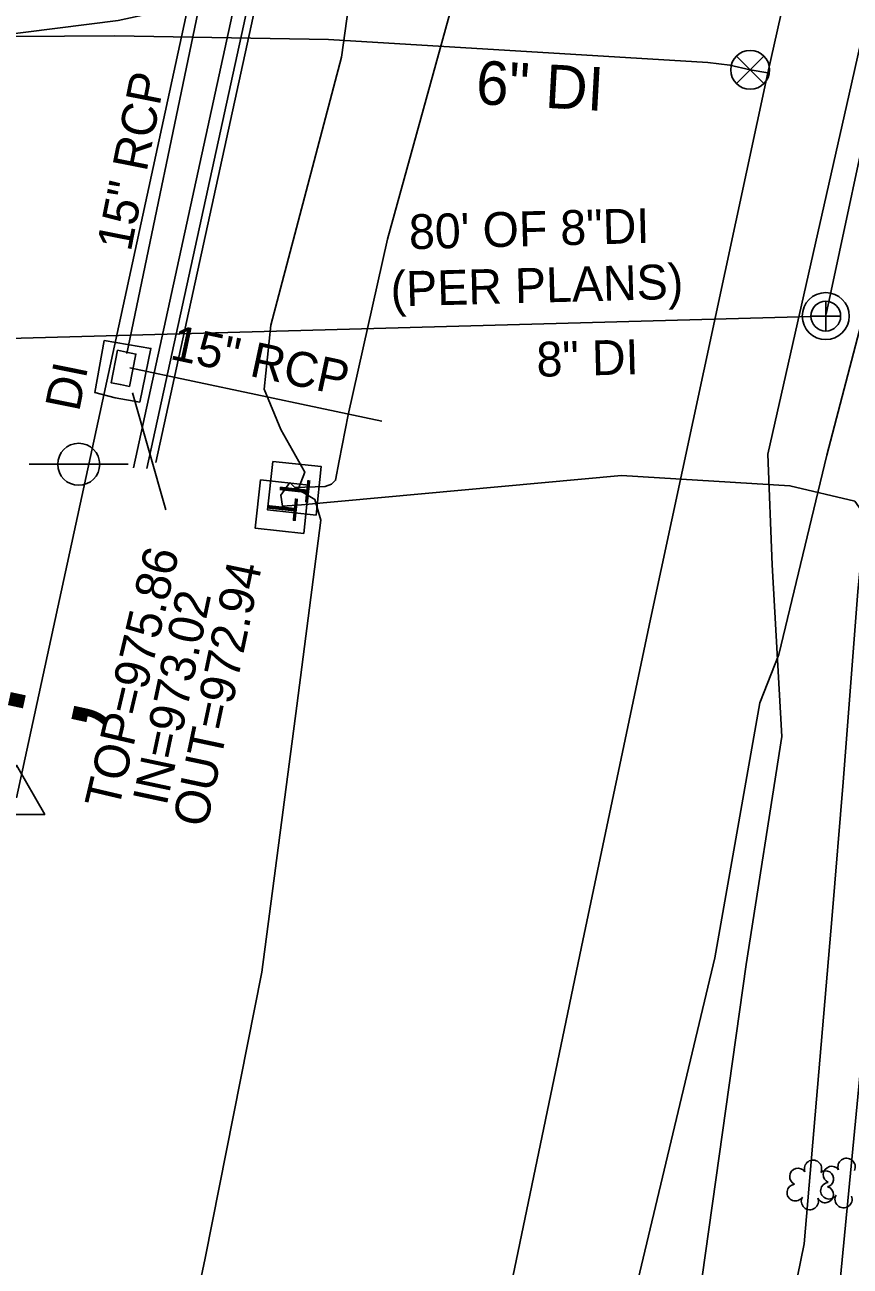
# Model space of a CAD drawing. Extents: x 1614611 to 1617571, y 898867 to 905462.
# Drawn here: x 1616119.9 to 1616214.6, y 899521.1 to 899663.5 of the extents above; entities that cross this region are included whole.
import ezdxf

# ---------------------------------------------------------------- set-up
doc = ezdxf.new("R2010")
doc.units = 0
for name, color, linetype in [('Exist Other Culture Area Outline', 7, 'Continuous'), ('Exist Right of Way Control of Access CA Symbol CELL', 7, 'Continuous'), ('Exist Right of Way Monument CELL', 7, 'Continuous'), ('Exist Structure Minor Drop Inlet Top Elevation', 7, 'Continuous'), ('Exist Structure Minor Pipes RCP 15 Inch Invert', 7, 'Continuous'), ('Exist Utilities Gas UG Line SUE LOS B', 7, 'Continuous'), ('Exist Utilities Sanitary Sewer UG Line', 7, 'Continuous'), ('Exist Utilities Sanitary Sewer UG Line Text', 7, 'Continuous'), ('Exist Utilities Telephone Pedestal CELL', 7, 'Continuous'), ('Exist Utilities Telephone Pole CELL', 7, 'Continuous'), ('Exist Utilities Telephone UG Cable SUE LOS B', 7, 'Continuous'), ('Exist Utilities Telephone UG Cable SUE LOS C', 7, 'Continuous'), ('Exist Utilities Telephone UG FO SUE LOS B', 7, 'Continuous'), ('Exist Utilities Water UG Line SUE LOS B', 7, 'Continuous'), ('Exist Utilities Water UG Line SUE LOS B Text', 7, 'Continuous'), ('Exist Vegetation Shrub CELL', 7, 'Continuous'), ('Old_Level_21', 7, 'Continuous'), ('Prop Drainage Structure Catch Basin Adjust CELL', 7, 'Continuous'), ('Prop Earthen Structure Head Ditch Label', 7, 'Continuous'), ('Prop Earthen Structure V Ditch Detail Label', 7, 'Continuous'), ('Prop Erosion Embankment Toe Protection CELL', 7, 'Continuous'), ('Prop Erosion Embankment Toe Protection with Rip Rap 2 Detail CELL', 7, 'Continuous'), ('Prop Plan Preparation Table Ditch Data CELL', 7, 'Continuous'), ('Raster_Level_3', 7, 'Continuous'), ('Scratch_Level_1', 7, 'Continuous')]:
    doc.layers.add(name, color=color, linetype=linetype)

msp = doc.modelspace()

# ---------------------------------------------------------------- linework, layer by layer
at = {"layer": 'Exist Other Culture Area Outline'}
for p, q in [((1616132.35, 899612.69), (1616166.46, 899769.17)), ((1616133.91, 899612.6), (1616167.96, 899768.77)), ((1616134.94, 899613.31), (1616168.8, 899768.62))]:
    msp.add_line(p, q, dxfattribs=at)
at = {"layer": 'Exist Right of Way Control of Access CA Symbol CELL'}
msp.add_line((1616122.06, 899589.2), (1616122.06, 899589.2), dxfattribs=at)
at = {"layer": 'Exist Right of Way Monument CELL'}
msp.add_line((1616220.81, 899596.37), (1616212.74, 899511.85), dxfattribs=at)
msp.add_lwpolyline([(1616115.7, 899572.93), (1616118.95, 899578.57), (1616122.19, 899572.93)], close=True, dxfattribs=at)
at = {"layer": 'Exist Utilities Gas UG Line SUE LOS B'}
for points in [[(1616187.46, 899507.75), (1616199.06, 899556.48), (1616204.23, 899585.74), (1616206.41, 899591.28), (1616211.93, 899614.15), (1616223.1, 899656.86), (1616229.69, 899682.98), (1616222.3, 899683.81), (1616195.98, 899689.93), (1616173.26, 899694.29), (1616178.09, 899708.89), (1616184.68, 899736.3), (1616189.66, 899759.77), (1616203.55, 899813.6), (1616203.95, 899815.38), (1616204.29, 899817.31), (1616212.67, 899859.04), (1616219.3, 899889.35), (1616228.95, 899933.49), (1616238.93, 899978.7)], [(1615883.75, 899646.31), (1615901.31, 899646.99), (1615935.64, 899648.33), (1615976.92, 899653.45), (1616023.28, 899655.53), (1616061.02, 899657.56), (1616095.16, 899659.54), (1616130.6, 899664), (1616152.67, 899668.83), (1616161.02, 899676.79), (1616162.72, 899678.72), (1616168.11, 899685.27), (1616173.26, 899694.29)]]:
    msp.add_lwpolyline(points, dxfattribs=at)
at = {"layer": 'Exist Utilities Sanitary Sewer UG Line'}
for p, q in [((1616211.84, 899630.34), (1616249.82, 899808.06)), ((1615898.34, 899621.47), (1616211.55, 899630.1))]:
    msp.add_line(p, q, dxfattribs=at)
at = {"layer": 'Exist Utilities Telephone Pedestal CELL'}
for p, q in [((1616150.87, 899610.42), (1616150.87, 899610.42)), ((1616149.45, 899608.3), (1616149.45, 899608.3))]:
    msp.add_line(p, q, dxfattribs=at)
for points in [[(1616148.35, 899613.42), (1616147.76, 899607.86), (1616153.32, 899607.27), (1616153.91, 899612.83), (1616148.35, 899613.42)], [(1616146.93, 899611.31), (1616146.34, 899605.75), (1616151.9, 899605.16), (1616152.49, 899610.72), (1616146.93, 899611.31)]]:
    msp.add_lwpolyline(points, dxfattribs=at)
at = {"layer": 'Exist Utilities Telephone Pole CELL'}
for p, q in [((1616120.4, 899613.1), (1616131.74, 899613.1)), ((1616126.08, 899613.1), (1616126.08, 899613.1))]:
    msp.add_line(p, q, dxfattribs=at)
msp.add_circle((1616126.08, 899613.1), 2.41, dxfattribs=at)
at = {"layer": 'Exist Utilities Telephone UG Cable SUE LOS B'}
for points in [[(1616150.87, 899610.42), (1616151.31, 899610.32), (1616152.04, 899612.2), (1616149.27, 899617.08), (1616147.35, 899621.71), (1616148.14, 899629.06), (1616156.25, 899659.82), (1616157.64, 899670.01), (1616158.07, 899672.03), (1616159.6, 899672.57), (1616170.4, 899676.62), (1616175.84, 899683.39), (1616181.23, 899693.06), (1616187.79, 899709.57), (1616199.04, 899757.59), (1616209.68, 899798.84), (1616219.37, 899841.05), (1616225.21, 899873.06), (1616225.37, 899875.48), (1616223.94, 899876.33), (1616214.88, 899878.3), (1616210.82, 899880.03)], [(1616102.33, 899364.7), (1616108.47, 899383.92), (1616109.56, 899394.84), (1616111.46, 899406.05), (1616113.78, 899415.32), (1616125.05, 899448.4), (1616131.48, 899478.87), (1616140.6, 899521.99), (1616147.11, 899554.84), (1616151.11, 899585.39), (1616153.86, 899606.67), (1616153.18, 899609.07), (1616150.87, 899610.42)]]:
    msp.add_lwpolyline(points, dxfattribs=at)
at = {"layer": 'Exist Utilities Telephone UG Cable SUE LOS C'}
msp.add_line((1616150.87, 899610.42), (1616150.3, 899611), dxfattribs=at)
msp.add_lwpolyline([(1616150.87, 899610.42), (1616154.37, 899610.53), (1616155.08, 899610.81), (1616155.56, 899611.27), (1616155.95, 899613.5), (1616157, 899618.76), (1616161.53, 899638.94), (1616170.89, 899672.88), (1616177.9, 899703.99), (1616183.82, 899729.81), (1616192.43, 899768.48), (1616200.55, 899801.86), (1616208.69, 899842.15), (1616214.79, 899872.35), (1616215.09, 899877.1), (1616210.82, 899880.03)], dxfattribs=at)
at = {"layer": 'Exist Utilities Telephone UG FO SUE LOS B'}
for points in [[(1616186.35, 899390.81), (1616176.34, 899400.32), (1616169.6, 899416.51), (1616168.42, 899428.4), (1616174.27, 899447.99), (1616183.34, 899477.46), (1616193.52, 899505.85), (1616197.61, 899519.87), (1616202.66, 899555.72), (1616206.78, 899581.86), (1616205.67, 899601.57), (1616205.17, 899614.27), (1616214.77, 899656.74), (1616223.26, 899694.54), (1616232.38, 899741.15), (1616238.03, 899772.42), (1616239.49, 899790.4), (1616242.07, 899803.13), (1616247.08, 899816.75), (1616255.84, 899848.11), (1616264.27, 899888.11), (1616275.63, 899938.03)], [(1616191.66, 899398.1), (1616189.9, 899399.55), (1616189.33, 899401.85), (1616189.51, 899413.84), (1616190.94, 899426.64), (1616199.92, 899477.56), (1616209.31, 899523.67), (1616212.53, 899561.31), (1616213.78, 899576.64), (1616215.47, 899598.51), (1616216.33, 899607.19), (1616215.12, 899608.85), (1616207.68, 899610.63), (1616188.38, 899611.81), (1616151.65, 899608.46), (1616149.45, 899608.3)], [(1616150.3, 899611), (1616149.29, 899609.57), (1616149.45, 899608.3)]]:
    msp.add_lwpolyline(points, dxfattribs=at)
at = {"layer": 'Exist Utilities Water UG Line SUE LOS B'}
for points in [[(1616133.06, 899355.12), (1616143.66, 899387.67), (1616153.34, 899426.63), (1616162.12, 899458.99), (1616173.96, 899510.49), (1616183.79, 899557.72), (1616191.69, 899595.33), (1616205.16, 899658.03), (1616213.77, 899696.35), (1616224.75, 899745.7), (1616235.9, 899798.65), (1616246.28, 899844.64), (1616246.68, 899847.05), (1616252.3, 899872.96), (1616263.66, 899921.5), (1616269.73, 899949.09)], [(1615884.52, 899649.89), (1615900.43, 899650.32), (1615934.08, 899652.41), (1615956.83, 899653.51), (1615976.81, 899654.81), (1616022.69, 899657.18), (1616038.37, 899658.07), (1616045.88, 899658.51), (1616063.31, 899659.84), (1616095.55, 899662.04), (1616130.24, 899662.26), (1616154.75, 899661.85), (1616198.28, 899659.21), (1616200.8, 899658.9), (1616203.13, 899658.36), (1616205.16, 899658.03)]]:
    msp.add_lwpolyline(points, dxfattribs=at)
at = {"layer": 'Exist Vegetation Shrub CELL'}
for p, q in [((1616210.11, 899530.23), (1616210.11, 899530.23)), ((1616213.97, 899530.45), (1616213.97, 899530.45))]:
    msp.add_line(p, q, dxfattribs=at)
for centre, radius, start, end in [((1616210.34, 899532.27), 0.99, 334.8391, 200.4717), ((1616214.19, 899532.49), 0.99, 334.8391, 200.4717), ((1616208.63, 899531.36), 0.968, 35.8908, 245.4216), ((1616211.78, 899531.1), 0.929, 284.4567, 126.0861), ((1616212.48, 899531.58), 0.968, 35.8908, 245.4216), ((1616208.31, 899529.53), 0.955, 95.1099, 327.9534), ((1616211.75, 899529.3), 0.937, 204.9913, 73.4601), ((1616212.17, 899529.75), 0.955, 95.1099, 327.9534), ((1616209.98, 899528.55), 0.984, 151.2797, 21.387), ((1616213.84, 899528.77), 0.984, 151.2797, 21.387)]:
    msp.add_arc(centre, radius, start, end, dxfattribs=at)
at = {"layer": 'Old_Level_21'}
msp.add_lwpolyline([(1616211.8, 899631.82), (1616211.8, 899628.39), (1616211.8, 899630.1), (1616213.51, 899630.1), (1616210.08, 899630.1)], dxfattribs=at)
for radius in [2.69, 1.71]:
    msp.add_circle((1616211.8, 899630.1), radius, dxfattribs=at)
at = {"layer": 'Prop Earthen Structure Head Ditch Label'}
msp.add_line((1616158.51, 899757.52), (1616118.95, 899574.82), dxfattribs=at)
at = {"layer": 'Prop Earthen Structure V Ditch Detail Label'}
msp.add_lwpolyline([(1616204.7, 899659.94), (1616201.55, 899656.79), (1616203.13, 899658.36), (1616204.7, 899656.79), (1616201.55, 899659.94)], dxfattribs=at)
msp.add_circle((1616203.13, 899658.36), 2.23, dxfattribs=at)
at = {"layer": 'Prop Erosion Embankment Toe Protection CELL'}
msp.add_lwpolyline([(1616131.9, 899622.03), (1616130.86, 899622.24), (1616129.79, 899622.46), (1616130.55, 899626.18), (1616131.57, 899625.97), (1616132.65, 899625.74)], close=True, dxfattribs=at)
at = {"layer": 'Prop Plan Preparation Table Ditch Data CELL'}
for p, q in [((1616131.6, 899625.8), (1616140.61, 899669.09)), ((1616131.94, 899624.16), (1616160.85, 899618.05))]:
    msp.add_line(p, q, dxfattribs=at)
at = {"layer": 'Raster_Level_3'}
msp.add_line((1616132.27, 899621.3), (1616136.09, 899607.86), dxfattribs=at)
at = {"layer": 'Scratch_Level_1'}
for points in [[(1616133.11, 899620.22), (1616130.27, 899620.73), (1616127.94, 899621.32), (1616128.99, 899627.3)], [(1616128.99, 899627.3), (1616134.36, 899626.39), (1616133.11, 899620.22)]]:
    msp.add_lwpolyline(points, dxfattribs=at)

# ---------------------------------------------------------------- texts
at = {"layer": 'Exist Right of Way Control of Access CA Symbol CELL'}
msp.add_text(';', height=12, rotation=77.7811, dxfattribs=at).set_placement((1616126.65, 899582.06))
at = {"layer": 'Exist Structure Minor Drop Inlet Top Elevation'}
msp.add_text('TOP=975.86', height=4, rotation=76.7039, dxfattribs=at).set_placement((1616130.63, 899573.35))
at = {"layer": 'Exist Structure Minor Pipes RCP 15 Inch Invert'}
for s, p in [('OUT=972.94', (1616140.74, 899571.31)), (' IN=973.02', (1616135.85, 899572.35))]:
    msp.add_text(s, height=4, rotation=78.0483, dxfattribs=at).set_placement(p)
at = {"layer": 'Exist Utilities Sanitary Sewer UG Line Text'}
for s, p in [('80\' OF 8"DI', (1616164.02, 899637.76)), ('(PER PLANS)', (1616161.92, 899631.2)), ('8" DI', (1616178.66, 899623.13))]:
    msp.add_text(s, height=4, rotation=1.5264, dxfattribs=at).set_placement(p)
at = {"layer": 'Exist Utilities Telephone Pedestal CELL'}
for p in [(1616149.29, 899611.72), (1616147.87, 899609.61)]:
    msp.add_text('T', height=3.42, rotation=263.9492, dxfattribs=at).set_placement(p)
at = {"layer": 'Exist Utilities Water UG Line SUE LOS B Text'}
msp.add_text('6" DI', height=5, rotation=356.8654, dxfattribs=at).set_placement((1616171.58, 899654.44))
at = {"layer": 'Prop Drainage Structure Catch Basin Adjust CELL'}
msp.add_text('DI', height=4, rotation=78.5982, dxfattribs=at).set_placement((1616126.12, 899619.03))
at = {"layer": 'Prop Erosion Embankment Toe Protection with Rip Rap 2 Detail CELL'}
for rotation, p in [(78.8283, (1616132.05, 899637.4)), (347.9834, (1616136.43, 899625.2))]:
    msp.add_text('15" RCP', height=4, rotation=rotation, dxfattribs=at).set_placement(p)

doc.saveas('drawing.dxf')
